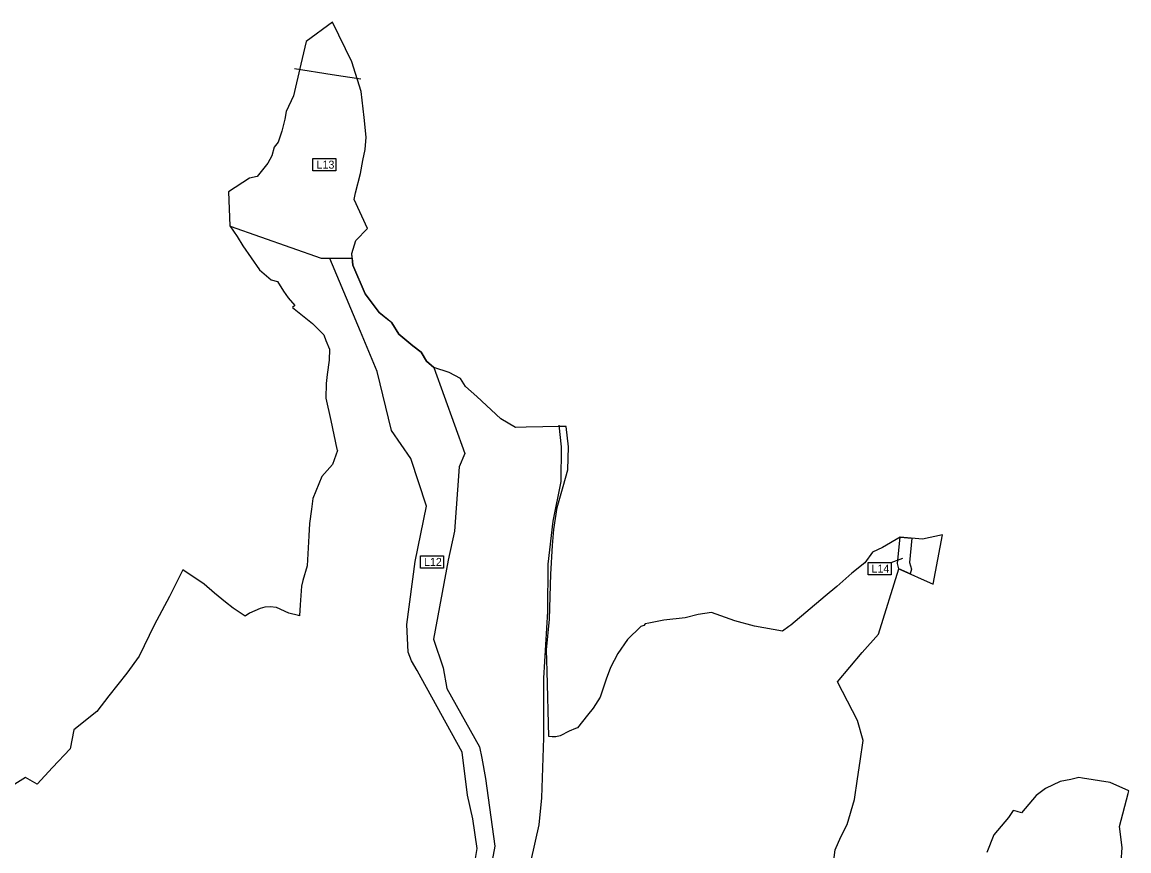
# Model space of a CAD drawing. Extents: x -547623 to -532764, y -1096714 to -1086523.
# Drawn here: x -540503 to -539120, y -1091535 to -1090500 of the extents above; entities that cross this region are included whole.
import ezdxf

# ---------------------------------------------------------------- set-up
doc = ezdxf.new("R2010")
doc.units = 0
for name, color, linetype in [('Vrstva 22', 7, 'Continuous'), ('Vrstva 32', 7, 'Continuous'), ('Vrstva 33', 7, 'Continuous'), ('Vrstva 36', 7, 'Continuous'), ('Vrstva 5', 7, 'Continuous')]:
    doc.layers.add(name, color=color, linetype=linetype)

msp = doc.modelspace()

# ---------------------------------------------------------------- linework, layer by layer
at = {"layer": 'Vrstva 22'}
for points in [[(-539489.6, -1091553.1), (-539487.2, -1091533.7), (-539480.1, -1091517.3), (-539472, -1091502), (-539463.2, -1091470.8), (-539459.2, -1091444.8), (-539456, -1091423), (-539452.1, -1091397.2), (-539459.1, -1091372.2), (-539484.2, -1091323.7), (-539453.6, -1091287.2), (-539433, -1091264.2), (-539407.4, -1091182.8), (-539364.8, -1091201.9), (-539352.9, -1091140.1), (-539378.2, -1091145.5), (-539406.1, -1091142.9), (-539428.1, -1091155.8), (-539440.7, -1091162), (-539450.1, -1091175.3), (-539466.2, -1091187.9), (-539484.9, -1091204.5), (-539499.8, -1091216.8), (-539542.7, -1091253.1), (-539545.1, -1091254.7), (-539553, -1091260.3), (-539587.9, -1091254.1), (-539612.3, -1091247.5), (-539641.7, -1091237.3), (-539658.3, -1091239.6), (-539674.5, -1091243.9), (-539701.4, -1091246.6), (-539720, -1091250.4), (-539724.4, -1091251.5), (-539726.2, -1091253.3), (-539730.1, -1091254.5), (-539746.8, -1091271), (-539758.7, -1091288.3), (-539768, -1091305.9), (-539773.2, -1091320.5), (-539780.6, -1091342.8), (-539789.6, -1091356.6), (-539796.4, -1091365.2), (-539809.1, -1091381.2), (-539811.5, -1091382.1), (-539819.5, -1091385.2), (-539830.9, -1091391.1), (-539836.2, -1091392.5), (-539840.7, -1091392.3), (-539844.9, -1091392.1), (-539847, -1091310.3), (-539847.8, -1091283.8), (-539844, -1091245.4), (-539842.2, -1091189.1), (-539840.2, -1091153.5), (-539838.5, -1091133.6), (-539834.3, -1091106), (-539826.9, -1091079.9), (-539821.1, -1091058.9), (-539820.2, -1091030.1), (-539823.4, -1091004.8), (-539831.6, -1091004.9), (-539873.2, -1091005.7), (-539886.7, -1091005.9), (-539904.8, -1090995.4), (-539934.9, -1090967.5), (-539949.1, -1090955), (-539955.3, -1090944.7), (-539969.5, -1090937.5), (-539988.7, -1090931.1), (-539997.6, -1090923.1), (-540004.2, -1090912), (-540014.9, -1090904), (-540032.2, -1090889.4), (-540040.9, -1090875.2), (-540056.7, -1090862.6), (-540074.2, -1090839), (-540089.8, -1090803.2), (-540091, -1090788.8), (-540086.2, -1090772.6), (-540071.4, -1090757.5), (-540088.3, -1090721.2), (-540086.3, -1090713), (-540080.3, -1090688.7), (-540077.1, -1090672.5), (-540074.4, -1090658.9), (-540073.2, -1090643.6), (-540075.6, -1090619.1), (-540079.2, -1090586.5), (-540091.2, -1090549.2), (-540115.1, -1090499.8), (-540147.9, -1090524), (-540154.6, -1090552.3), (-540163.8, -1090591.8), (-540172.9, -1090611.3), (-540174.9, -1090620.8), (-540178.6, -1090636), (-540183.2, -1090649.8), (-540187.9, -1090656.1), (-540190.9, -1090666.9), (-540195.9, -1090676.1), (-540209.4, -1090692.6), (-540218.7, -1090694.7), (-540244.9, -1090711.7), (-540243.3, -1090754.4), (-540234.3, -1090767.6), (-540227.1, -1090779), (-540206.3, -1090809.2), (-540191.6, -1090821.5), (-540183.9, -1090823.6), (-540176.3, -1090835.8), (-540170.5, -1090844.1), (-540162.2, -1090853.8), (-540165.2, -1090856.1), (-540140.1, -1090876.2), (-540126, -1090890.4), (-540123.3, -1090897.3), (-540119.1, -1090908.1), (-540119.2, -1090921.8), (-540121.7, -1090939.9), (-540122.9, -1090951.2), (-540123.6, -1090969.4), (-540117.3, -1090997.5), (-540109.8, -1091033.1), (-540108.8, -1091034.7), (-540115.1, -1091052.4), (-540128.6, -1091067.4), (-540139.8, -1091094.6), (-540141.6, -1091108), (-540143.7, -1091126.1), (-540144.9, -1091141.3), (-540147, -1091178.9), (-540152.2, -1091197.2), (-540153.9, -1091204.2), (-540155.6, -1091227.6), (-540156.3, -1091241.3), (-540157.8, -1091240.9), (-540169.7, -1091237.9), (-540185.2, -1091231), (-540192.9, -1091229.9), (-540199.9, -1091230.4), (-540205.4, -1091232.1), (-540218.8, -1091238), (-540224.2, -1091241.8), (-540239.2, -1091231.7), (-540249, -1091224.1), (-540262.4, -1091212.8), (-540275.7, -1091201.9), (-540302, -1091183.8), (-540309.6, -1091199), (-540318.7, -1091217.1), (-540338, -1091253), (-540356.9, -1091291.5), (-540372, -1091312.8), (-540394.4, -1091341.3), (-540409.6, -1091360.8), (-540438.2, -1091383.8), (-540442.8, -1091407.6), (-540464.8, -1091430.7), (-540484.1, -1091451.4), (-540498.8, -1091443.1), (-540523.2, -1091458.6)], [(-540079.9, -1090571.1), (-540115.7, -1090565.5), (-540162.6, -1090558.2)], [(-539129.8, -1091549), (-539128.5, -1091530.6), (-539132, -1091504.6), (-539121.2, -1091463.1), (-539120.2, -1091459.7), (-539143.6, -1091449.3), (-539178.2, -1091443.9), (-539182.6, -1091443.3), (-539192.7, -1091445.7), (-539205.9, -1091448.2), (-539224.2, -1091456.8), (-539236.2, -1091465.9), (-539254.3, -1091487.4), (-539259.8, -1091485.8), (-539264.8, -1091484.3), (-539270.6, -1091493.1), (-539289, -1091514.9), (-539297.7, -1091536.7)]]:
    msp.add_lwpolyline(points, dxfattribs=at)
at = {"layer": 'Vrstva 32'}
msp.add_lwpolyline([(-540090.5, -1090794.8), (-540091, -1090788.8), (-540086.2, -1090772.6), (-540071.4, -1090757.5), (-540088.3, -1090721.2), (-540086.3, -1090713), (-540080.3, -1090688.7), (-540077.1, -1090672.5), (-540074.4, -1090658.9), (-540073.2, -1090643.6), (-540075.6, -1090619.1), (-540079.2, -1090586.5), (-540091.2, -1090549.2), (-540115.1, -1090499.8), (-540147.9, -1090524), (-540154.6, -1090552.3), (-540163.8, -1090591.8), (-540172.9, -1090611.3), (-540174.9, -1090620.8), (-540178.6, -1090636), (-540183.2, -1090649.8), (-540187.9, -1090656.1), (-540190.9, -1090666.9), (-540195.9, -1090676.1), (-540209.4, -1090692.6), (-540218.7, -1090694.7), (-540244.9, -1090711.7), (-540243.3, -1090754.4), (-540243.2, -1090754.5), (-540129.5, -1090794.4), (-540115.7, -1090794.5), (-540106.4, -1090794.6), (-540103.3, -1090794.6), (-540090.5, -1090794.8)], dxfattribs=at)
at = {"layer": 'Vrstva 33'}
for points in [[(-539936.7, -1091544.3), (-539934.3, -1091531.7), (-539940, -1091494.8), (-539946.6, -1091465.4), (-539953.2, -1091411.4), (-540004.4, -1091318.6), (-540009.5, -1091309.6), (-540016.3, -1091297.6), (-540016.3, -1091297.4), (-540020.7, -1091286.6), (-540022.1, -1091252.3), (-540011.9, -1091173.5), (-539997.6, -1091104.4), (-540017.5, -1091044.9), (-540041.3, -1091010), (-540059.5, -1090936.2), (-540080.3, -1090886.3), (-540118.3, -1090795.1), (-540115.7, -1090794.5), (-540106.4, -1090794.6), (-540103.3, -1090794.6), (-540090.5, -1090794.8), (-540089.8, -1090803.2), (-540074.2, -1090839), (-540056.7, -1090862.6), (-540044.6, -1090872.2), (-540040.9, -1090875.2), (-540032.2, -1090889.4), (-540014.9, -1090904), (-540004.2, -1090912), (-539997.6, -1090923.1), (-539988.7, -1090931.1), (-539950, -1091038.6), (-539957.1, -1091055.2), (-539962.7, -1091135.4), (-539970.6, -1091171.9), (-539988.9, -1091270.3), (-539977, -1091306.1), (-539972.2, -1091331.9), (-539931.5, -1091404.8), (-539928.6, -1091419), (-539923.9, -1091444.6), (-539912.5, -1091528.9), (-539915.5, -1091546.9)], [(-539391.2, -1091144.3), (-539394.1, -1091174.6), (-539391.7, -1091182.9), (-539393.6, -1091188.9), (-539407.4, -1091182.8), (-539409.3, -1091176.1), (-539408.9, -1091171.6), (-539406.1, -1091142.9), (-539391.2, -1091144.3)]]:
    msp.add_lwpolyline(points, dxfattribs=at)
at = {"layer": 'Vrstva 36'}
msp.add_line((-539417.2, -1091174.5), (-539402.8, -1091169.4), dxfattribs=at)
for points in [[(-540139.6, -1090670.1), (-540110.9, -1090670.1), (-540110.9, -1090685.5), (-540139.6, -1090685.5)], [(-540005.2, -1091166.3), (-539976.6, -1091166.3), (-539976.6, -1091181.8), (-540005.2, -1091181.8)], [(-539445.9, -1091174.5), (-539417.2, -1091174.5), (-539417.2, -1091190), (-539445.9, -1091190)]]:
    msp.add_lwpolyline(points, close=True, dxfattribs=at)
at = {"layer": 'Vrstva 5'}
msp.add_lwpolyline([(-539866.8, -1091546.8), (-539857.1, -1091502.2), (-539853.6, -1091468.8), (-539851.2, -1091393.5), (-539851.2, -1091319), (-539846.1, -1091235.9), (-539845.6, -1091176.9), (-539839.6, -1091122.9), (-539829.5, -1091073.7), (-539828.9, -1091030.4), (-539831.8, -1091003.2)], dxfattribs=at)

# ---------------------------------------------------------------- texts
at = {"layer": 'Vrstva 36'}
for s, p in [('L13', (-540135.1, -1090682.8)), ('L12', (-540000.9, -1091179)), ('L14', (-539441.7, -1091187.3))]:
    msp.add_text(s, height=10, dxfattribs=at).set_placement(p)

doc.saveas('drawing.dxf')
